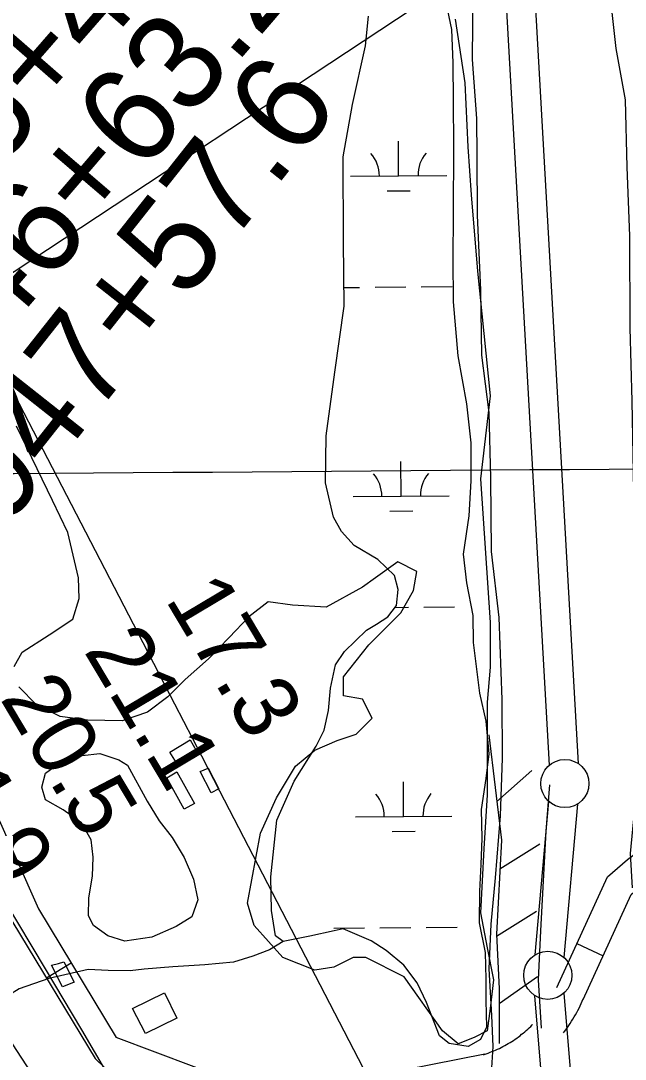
# Model space of a CAD drawing. Extents: x 3540316 to 3578335, y 553172 to 578787.
# Drawn here: x 3552350 to 3552978, y 564084 to 565162 of the extents above; entities that cross this region are included whole.
import ezdxf

# ---------------------------------------------------------------- set-up
doc = ezdxf.new("R2010")
doc.units = 0
for name, color, linetype in [('V-BLDG-OTLN', 7, 'Continuous'), ('V-BRDG-OTLN', 7, 'Continuous'), ('V-FLOD-BASE', 7, 'Continuous'), ('V-GRID-MAJR', 7, 'Continuous'), ('V-LEVE-TOET', 7, 'Continuous'), ('V-RIVR-RANG', 7, 'Continuous'), ('V-ROAD-CNTR', 7, 'Continuous'), ('V-RRAP-FSHR', 7, 'Continuous'), ('V-SITE-VEGE', 7, 'Continuous'), ('V-SURV-IDEN', 7, 'Continuous'), ('V-SURV-LINE', 7, 'Continuous'), ('V-TOPO-MINR', 7, 'Continuous'), ('V-TOPO-SHOR', 7, 'Continuous'), ('V-WETL-SWMP', 7, 'Continuous')]:
    doc.layers.add(name, color=color, linetype=linetype)

msp = doc.modelspace()

# ---------------------------------------------------------------- linework, layer by layer
at = {"layer": 'V-BLDG-OTLN'}
for points in [[(3552532.5, 564404.5), (3552511.9, 564391.8), (3552505.1, 564402.8), (3552526.1, 564415.7)], [(3552544.8, 564386.2), (3552555.9, 564364.7), (3552547.9, 564360.5), (3552536.4, 564382.7)], [(3552512.3, 564382.4), (3552530.6, 564349.6), (3552520, 564343.7), (3552501.9, 564376.2)], [(3552466.2, 564136.4), (3552499.4, 564152.7), (3552512.2, 564126.6), (3552479.9, 564110.7)]]:
    msp.add_lwpolyline(points, close=True, dxfattribs=at)
at = {"layer": 'V-BRDG-OTLN'}
msp.add_lwpolyline([(3552395.1, 564185.1), (3552405.8, 564164), (3552399.8, 564161.6), (3552393.7, 564159.2), (3552382.2, 564181.4), (3552389.3, 564183.4)], close=True, dxfattribs=at)
at = {"layer": 'V-FLOD-BASE'}
msp.add_lwpolyline([(3552890.9, 564116.1), (3552887.8, 564166.3), (3552890.1, 564217.3), (3552895.7, 564320.8), (3552899.7, 564368.7)], dxfattribs=at)
at = {"layer": 'V-GRID-MAJR'}
msp.add_spline([(3544475.4, 564634.2), (3549748.1, 564672.9), (3555020.8, 564712.4), (3560293.6, 564752.7), (3565566.3, 564793.7), (3570839, 564835.5), (3576111.7, 564878.1)], degree=3, dxfattribs=at)
at = {"layer": 'V-LEVE-TOET'}
for points in [[(3552793.2, 565538.8), (3552825.9, 565514.8), (3552849.2, 565491.8), (3552867.3, 565469.2), (3552885.6, 565441.1), (3552899.4, 565418.9), (3552921.2, 565380.7), (3552933.2, 565353.3), (3552941.7, 565317.3), (3552948.7, 565268), (3552959.2, 565215.2), (3552968, 565133.8), (3552977.8, 565080.2), (3552979.4, 565010.4), (3552982.3, 564939.1), (3552982.6, 564843.5), (3552984.7, 564767.2), (3552986.6, 564655.9), (3552989.5, 564577.6), (3552993.1, 564455), (3552989.4, 564366), (3552982.8, 564297.4), (3552985, 564262)], [(3552839.3, 564074.9), (3552840.7, 564096.9), (3552839.3, 564129.4), (3552836.6, 564177.6), (3552838.7, 564224.2), (3552843, 564272.4), (3552848.5, 564336.7), (3552850.4, 564396.7), (3552850, 564457.4), (3552847, 564542.8), (3552839.1, 564611.3), (3552838.2, 564687.7), (3552836.5, 564755.5), (3552829.1, 564815), (3552827.8, 564882.7), (3552824.5, 564960.7), (3552824.1, 565021.8), (3552823.8, 565061), (3552819.1, 565122.4), (3552819.8, 565196.5)]]:
    msp.add_lwpolyline(points, dxfattribs=at)
at = {"layer": 'V-RIVR-RANG'}
msp.add_line((3552858.7, 565242), (3552174.3, 564790.2), dxfattribs=at)
at = {"layer": 'V-ROAD-CNTR'}
for p, q in [((3552927.6, 564204), (3552954.9, 564191.4)), ((3552402.7, 564183.7), (3552377, 564168.2))]:
    msp.add_line(p, q, dxfattribs=at)
for points in [[(3552274.2, 564452.3), (3552368.8, 564239.9), (3552449.4, 564106.3)], [(3552246.8, 564440.1), (3552342.1, 564226), (3552427.5, 564084.7)], [(3552906.8, 564158.5), (3552959.5, 564273.4), (3552980.1, 564291.2), (3553018.9, 564320.4)], [(3552934, 564146), (3552984, 564254.9), (3552999, 564267.8), (3553019.8, 564283.5)], [(3552913.7, 564111.2), (3552914.7, 564112.5), (3552916.2, 564114.5), (3552917.8, 564116.7), (3552919.3, 564118.9), (3552920.8, 564121), (3552922.2, 564123.2), (3552923.6, 564125.5), (3552924.9, 564127.7), (3552926.3, 564130), (3552927.5, 564132.3), (3552928.7, 564134.6), (3552929.9, 564137), (3552931.1, 564139.4), (3552932.2, 564141.7), (3552933.2, 564144.1), (3552934.2, 564146.5)], [(3552830.5, 564088.6), (3552831.5, 564088.9), (3552833.5, 564089.6), (3552835.5, 564090.3), (3552837.5, 564091), (3552839.4, 564091.7), (3552841.4, 564092.5), (3552843.3, 564093.4), (3552845.2, 564094.2), (3552847.2, 564095.1), (3552849.1, 564096), (3552850.9, 564097), (3552852.8, 564098), (3552854.6, 564099), (3552856.4, 564100.1), (3552858.3, 564101.2), (3552860, 564102.3), (3552861.8, 564103.4), (3552863.6, 564104.6), (3552865.3, 564105.8), (3552866.9, 564107.1), (3552868.6, 564108.3), (3552870.3, 564109.7), (3552871.9, 564111), (3552873.5, 564112.3), (3552875.1, 564113.7), (3552876.7, 564115.1), (3552878.2, 564116.6), (3552879.7, 564118), (3552881.2, 564119.5), (3552881.6, 564120)], [(3552832.1, 564089), (3552611.4, 564045.3), (3552449.4, 564106.3)], [(3552427.5, 564084.7), (3552447.1, 564065.6), (3552464.8, 564047.7), (3552482.3, 564029.4), (3552499.6, 564010.8), (3552516.4, 563992), (3552532.9, 563972.8), (3552536.6, 563968.4)]]:
    msp.add_lwpolyline(points, dxfattribs=at)
at = {"layer": 'V-RRAP-FSHR'}
for p, q in [((3552844.5, 564351.4), (3552880.9, 564383.9)), ((3552847.8, 564281.7), (3552889.1, 564307.7)), ((3552844.3, 564211.8), (3552885.6, 564237.7)), ((3552846.9, 564141.8), (3552886.9, 564169.9))]:
    msp.add_line(p, q, dxfattribs=at)
msp.add_lwpolyline([(3552836.3, 564420.9), (3552849.2, 564311.4), (3552844.3, 564213.6), (3552846.9, 564156.8), (3552847, 564100.1)], dxfattribs=at)
at = {"layer": 'V-SITE-VEGE'}
for points in [[(3552801.2, 565164.2), (3552811.2, 565097.9), (3552814.5, 565031.6), (3552817.8, 564981.8), (3552824.4, 564902.3), (3552837.7, 564773), (3552827.7, 564686.7), (3552837.7, 564537.6), (3552837.7, 564491.1), (3552834.4, 564454.7), (3552834.4, 564358.5), (3552831, 564302.2), (3552827.7, 564235.8), (3552834.4, 564199.4), (3552841, 564166.2), (3552837.7, 564136.4), (3552834.4, 564113.2), (3552821.1, 564106.5), (3552804.5, 564099.9), (3552788, 564113.2), (3552748.2, 564169.5), (3552708.4, 564189.4), (3552695.2, 564189.4), (3552675.3, 564179.5), (3552655.4, 564176.2), (3552622.3, 564189.4), (3552592.5, 564222.6), (3552585.8, 564245.8), (3552599.1, 564318.7), (3552615.7, 564355.2), (3552635.5, 564388.4), (3552655.4, 564404.9), (3552678.6, 564414.9), (3552698.5, 564421.5), (3552715.1, 564438.1), (3552705.1, 564458), (3552685.2, 564461.3), (3552685.2, 564481.2), (3552711.7, 564514.3), (3552731.6, 564534.2), (3552744.9, 564547.5), (3552758.1, 564570.7), (3552761.5, 564590.6), (3552741.6, 564600.5), (3552718.4, 564584), (3552705.1, 564574), (3552667.3, 564553.4), (3552632.5, 564555.6), (3552607, 564558.9), (3552587, 564543.5), (3552566.6, 564521.8), (3552545.1, 564499.6), (3552520.8, 564478.4), (3552502.8, 564460.1), (3552481.8, 564444.3), (3552455.5, 564435.3), (3552419.7, 564436.1), (3552391.2, 564439.8), (3552366.7, 564451.9), (3552348.4, 564470.8)], [(3552343.4, 564491.9), (3552351.6, 564506.6), (3552379.9, 564524.5), (3552404.3, 564540.8), (3552411, 564562.4), (3552410.3, 564583.9), (3552399.2, 564630.9), (3552383.3, 564664.1), (3552346, 564741.3)]]:
    msp.add_lwpolyline(points, dxfattribs=at)
msp.add_lwpolyline([(3552461, 564389.4), (3552481.4, 564351.8), (3552493.8, 564331.3), (3552507.6, 564314.3), (3552520, 564293.3), (3552529.5, 564270.8), (3552534.1, 564249.3), (3552527.8, 564231.6), (3552511.7, 564221.7), (3552486.3, 564210.7), (3552458.4, 564206.6), (3552440.7, 564211.9), (3552425.9, 564222.6), (3552420.5, 564232.8), (3552420.8, 564251.4), (3552424.6, 564274), (3552425.4, 564293.6), (3552423.4, 564311.7), (3552413.4, 564329.3), (3552394.2, 564342.9), (3552376, 564353.1), (3552372, 564366.3), (3552375.8, 564381), (3552391.4, 564392.4), (3552413.9, 564399.4), (3552432.5, 564401.5), (3552452.2, 564394.8)], close=True, dxfattribs=at)
at = {"layer": 'V-SURV-LINE'}
for points in [[(3552899.1, 564389.3), (3552853.4, 565198.2)], [(3552883.3, 565199.9), (3552929, 564391)], [(3552884.2, 564192.2), (3552898.5, 564351.6)], [(3552928.4, 564348.9), (3552914.1, 564189.5)], [(3552936.4, 563520.2), (3552884.1, 564149.8)], [(3552914, 564152.3), (3552966.3, 563522.7)]]:
    msp.add_lwpolyline(points, dxfattribs=at)
for centre in [(3552915.2, 564370.2), (3552897.4, 564171)]:
    msp.add_circle(centre, 25, dxfattribs=at)
at = {"layer": 'V-TOPO-MINR'}
for points in [[(3552450.7, 564051), (3552413.6, 564114.4), (3552376.1, 564177.7), (3552333.3, 564249.2), (3552316.6, 564276.3), (3552299.3, 564303), (3552281.1, 564329.1), (3552262.3, 564354.8), (3551604.2, 565228.5), (3551581.5, 565257.9), (3551558.3, 565286.8), (3551534.2, 565315.1), (3551509.7, 565343), (3551484.6, 565370.4), (3551459, 565397.3), (3551433, 565423.8), (3551406.5, 565449.9), (3550894.9, 565944.3)], [(3552460.9, 563917), (3552321.3, 564130.6), (3552314.1, 564141.7), (3552307, 564152.8), (3552299.8, 564163.9), (3552292.7, 564175), (3552285.6, 564186.2), (3552278.5, 564197.3), (3552271.4, 564208.4), (3552264.2, 564219.4), (3552256.7, 564230.9), (3552245.6, 564247.6), (3552234.3, 564264.1), (3552222.8, 564280.5), (3552211.1, 564296.8), (3552124.8, 564414.9), (3552069.6, 564490), (3552014.3, 564565), (3551958.8, 564639.8), (3551903.1, 564714.4), (3551433.3, 565341.9)], [(3552290.4, 564916.8), (3552305.3, 564868.3), (3552313.3, 564844.3), (3552322.3, 564820.7), (3552332.4, 564797.6), (3552343.5, 564774.8), (3552482, 564507.2), (3552500.7, 564471.1), (3552519.3, 564435), (3552538, 564398.8), (3552556.7, 564362.7), (3553127.9, 563259.2)]]:
    msp.add_lwpolyline(points, dxfattribs=at)
at = {"layer": 'V-TOPO-SHOR'}
msp.add_lwpolyline([(3552622.7, 564206.1), (3552608.4, 564197.5), (3552591.1, 564190.8), (3552571.2, 564184.8), (3552541.5, 564182), (3552508.2, 564179.8), (3552478.5, 564177.3), (3552463.8, 564175.6), (3552440.9, 564176.1), (3552420.3, 564176.9), (3552379.5, 564167.8), (3552348.5, 564156.8), (3552338.6, 564150.8)], dxfattribs=at)
at = {"layer": 'V-WETL-SWMP'}
for p, q in [((3552742.6, 565001.4), (3552742.3, 565037.4)), ((3552692.6, 565001), (3552792.6, 565001.7)), ((3552730.7, 564985.8), (3552754.7, 564986)), ((3552685.9, 564885.5), (3552702.1, 564885.6)), ((3552718.1, 564885.7), (3552750.1, 564886)), ((3552766.1, 564886.1), (3552798.1, 564886.4)), ((3552745.2, 564668.7), (3552744.9, 564704.7)), ((3552695.2, 564668.3), (3552795.2, 564669.1)), ((3552733.3, 564653.2), (3552757.3, 564653.4)), ((3552738.9, 564553.2), (3552752.7, 564553.3)), ((3552768.7, 564553.4), (3552800.7, 564553.7)), ((3552747.7, 564336), (3552747.5, 564372)), ((3552697.8, 564335.6), (3552797.7, 564336.4)), ((3552735.9, 564320.5), (3552759.9, 564320.7)), ((3552675.2, 564220), (3552707.2, 564220.3)), ((3552723.2, 564220.4), (3552755.2, 564220.7)), ((3552771.2, 564220.8), (3552803.2, 564221))]:
    msp.add_line(p, q, dxfattribs=at)
msp.add_lwpolyline([(3552790.2, 565188.4), (3552797.3, 565153.3), (3552799, 565118.7), (3552799.3, 565079.1), (3552799.6, 565032.7), (3552799.1, 564960.4), (3552799, 564915.5), (3552799.3, 564870.6), (3552804.1, 564814.4), (3552813.2, 564764.7), (3552817.4, 564724.2), (3552817.7, 564684.6), (3552815.5, 564648.4), (3552809.4, 564608.3), (3552813, 564578.6), (3552819.6, 564544.9), (3552819.8, 564516.6), (3552826.5, 564463.9), (3552833.1, 564435.1), (3552836.2, 564401), (3552833, 564375.5), (3552828.3, 564343.3), (3552829, 564313.5), (3552827.8, 564286.1), (3552826.5, 564258.3), (3552826.2, 564225.6), (3552832.3, 564194.8), (3552833, 564167), (3552833.1, 564145), (3552833.8, 564117.2), (3552827.5, 564104.4), (3552814.9, 564097), (3552794.9, 564100.3), (3552785, 564108.1), (3552771.6, 564142.6), (3552761.7, 564163.1), (3552747.9, 564181.5), (3552729.7, 564196.6), (3552714, 564206.7), (3552685.1, 564219.2), (3552675.8, 564217.2), (3552650.5, 564211.6), (3552622.7, 564206.1), (3552614.8, 564211.9), (3552610.7, 564238.2), (3552610, 564273.4), (3552616, 564332), (3552634.2, 564372.7), (3552656.9, 564409), (3552665.1, 564425.7), (3552669.9, 564446.2), (3552671.7, 564469.2), (3552676.9, 564493.6), (3552686.5, 564507.4), (3552709.3, 564529.5), (3552719.5, 564535.9), (3552731.2, 564543.3), (3552740.4, 564555.1), (3552742.2, 564571.7), (3552738.2, 564586.4), (3552721, 564602.9), (3552696.5, 564617.3), (3552683.2, 564631.9), (3552674.8, 564647), (3552666.8, 564682.6), (3552667.4, 564731.4), (3552676.2, 564797.4), (3552686, 564865.9), (3552685.5, 564933.3), (3552684.9, 565021.2), (3552694.8, 565075.4), (3552708, 565136.6), (3552711.3, 565167.4)], dxfattribs=at)
for centre, start, end in [((3552687.4, 565001.4), 359.6699, 41.2135), ((3552797.9, 565002.3), 139.6699, 181.2135), ((3552689.9, 564668.7), 359.6699, 41.2135), ((3552800.4, 564669.6), 139.6699, 181.2135), ((3552692.5, 564336.1), 359.6699, 41.2135), ((3552803, 564336.9), 139.6699, 181.2135)]:
    msp.add_arc(centre, 35.2, start, end, dxfattribs=at)

# ---------------------------------------------------------------- texts
at = {"layer": 'V-RIVR-RANG'}
for s, p in [('17.3', (3552499.6, 564561.6)), ('21.1', (3552415, 564508.2)), ('20.5', (3552328, 564458.8)), ('21.9', (3552242.1, 564407.6))]:
    msp.add_text(s, height=67, rotation=300.7883, dxfattribs=at).set_placement(p)
at = {"layer": 'V-SURV-IDEN'}
for s, rotation, p in [('4945+44.2', 48.9049, (3552179.3, 564838.3)), ('4946+63.2', 49.4335, (3552231.5, 564717.3)), ('4947+57.6', 51.678, (3552288.3, 564575.6))]:
    msp.add_text(s, height=100, rotation=rotation, dxfattribs=at).set_placement(p)

doc.saveas('drawing.dxf')
